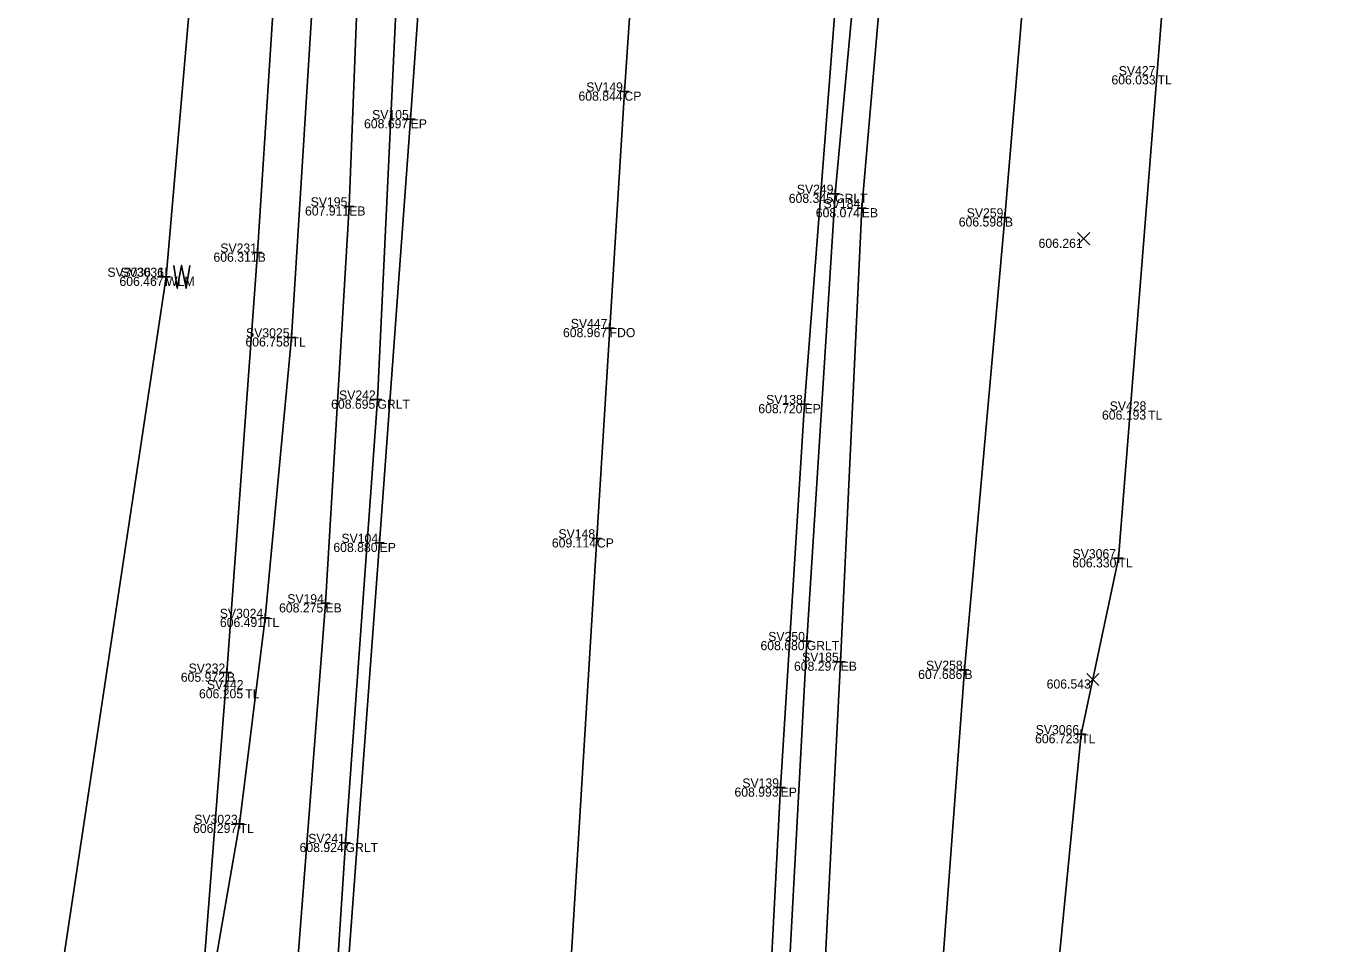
# Model space of a CAD drawing. Extents: x -2 to 1979875, y -2 to 232027.
# Drawn here: x 1978751.3 to 1978823.1, y 231361.9 to 231412.1 of the extents above; entities that cross this region are included whole.
import ezdxf

# ---------------------------------------------------------------- set-up
doc = ezdxf.new("R2010")
doc.units = 0
for name, color, linetype in [('_CIVIL_CONSTRUCTION', 7, 'Continuous'), ('GE_P_Alignment', 7, 'Continuous'), ('GE_P_Alignment_1000_Curve_Data', 7, 'Continuous'), ('GE_P_Alignment_100_Curve_Data', 7, 'Continuous'), ('GE_P_Alignment_500_Curve_Data', 7, 'Continuous'), ('GE_X_Alignment', 7, 'Continuous'), ('GE_X_Alignment_1000_Curve_Data', 7, 'Continuous'), ('GE_X_Alignment_1000_Stations', 7, 'Continuous'), ('GE_X_Alignment_100_Curve_Data', 7, 'Continuous'), ('GE_X_Alignment_100_Stations', 7, 'Continuous'), ('SC_Scratch1', 7, 'Continuous'), ('SV_X_Random_Point', 7, 'Continuous'), ('UT_X_Water', 7, 'Continuous'), ('UT_X_Water_Cells', 7, 'Continuous')]:
    doc.layers.add(name, color=color, linetype=linetype)

msp = doc.modelspace()

# ---------------------------------------------------------------- linework, layer by layer
at = {"layer": 'GE_P_Alignment'}
for points in [[(1978861.689, 231782.415), (1978851.853, 231763.969), (1978841.987, 231745.294), (1978832.802, 231726.204), (1978823.63, 231707.125), (1978815.734, 231686.751), (1978809.08, 231664.461), (1978799.472, 231640.53), (1978791.914, 231616.771), (1978786.956, 231593.117), (1978782.497, 231568.131), (1978778.452, 231542.695), (1978775.331, 231517.531), (1978773.11, 231494.147), (1978771.443, 231473.021), (1978766.839, 231446.726), (1978765.415, 231421.944), (1978763.995, 231399.725), (1978762.317, 231376.717), (1978760.52, 231353.776), (1978758.484, 231331.627), (1978756.746, 231315.247), (1978755.236, 231305.004), (1978757.214, 231296.936)], [(1978796.543, 231298.857), (1978798.274, 231324.443), (1978800.704, 231350.055), (1978802.691, 231376.873), (1978804.911, 231401.653), (1978806.885, 231425.398), (1978807.692, 231450.453), (1978809.926, 231474.524), (1978811.781, 231491.704), (1978814.624, 231521.225), (1978818.445, 231546.214), (1978822.849, 231572.066), (1978827.059, 231594.68), (1978834.582, 231618.811), (1978841.486, 231643.192), (1978848.448, 231666.52), (1978859.661, 231691.186), (1978869.566, 231712.589), (1978880.404, 231735.407), (1978890.398, 231756.483), (1978895.241, 231765.92)]]:
    msp.add_lwpolyline(points, dxfattribs=at)
at = {"layer": 'GE_P_Alignment_1000_Curve_Data'}
for points in [[(1978733.125, 231254.651), (1978737.318, 231281.706), (1978740.694, 231296.926), (1978742.413, 231306.837), (1978748.228, 231322.336), (1978755.317, 231333.122), (1978758.78, 231344.165), (1978763.011, 231368.433), (1978764.4, 231379.716), (1978765.858, 231395.082), (1978767.238, 231417.341), (1978767.097, 231431.457), (1978767.532, 231441.077), (1978768.449, 231451.786), (1978770.871, 231461.5), (1978774.002, 231474.92), (1978775.889, 231489.026), (1978776.895, 231504.336), (1978777.94, 231514.653)], [(1978800.253, 231250.204), (1978805.284, 231291.391), (1978804.508, 231297.592), (1978804.78, 231306.073), (1978804.463, 231312.372), (1978805.146, 231324.315), (1978805.161, 231336.373), (1978807.189, 231350.111), (1978807.848, 231360.671), (1978809.086, 231373.348), (1978811.125, 231382.982), (1978814.162, 231421.098), (1978816.965, 231468.048), (1978822.427, 231510.515)]]:
    msp.add_lwpolyline(points, dxfattribs=at)
at = {"layer": 'GE_P_Alignment_100_Curve_Data'}
for points in [[(1978764.438, 231298.773), (1978765.712, 231320.829), (1978767.378, 231345.616), (1978768.807, 231367.39), (1978770.554, 231391.673), (1978771.722, 231416.416), (1978771.842, 231435.288), (1978771.576, 231449.202)], [(1978801.365, 231447.686), (1978797.734, 231425.84), (1978795.609, 231402.949), (1978794.056, 231378.448), (1978792.74, 231353.579), (1978790.842, 231329.19), (1978789.312, 231307.337), (1978788.697, 231297.789)]]:
    msp.add_lwpolyline(points, dxfattribs=at)
at = {"layer": 'GE_P_Alignment_500_Curve_Data'}
for p, q in [((1978783.265, 231395.844), (1978783.265, 231395.344)), ((1978783.015, 231395.594), (1978783.515, 231395.594)), ((1978783.265, 231395.594), (1978783.265, 231395.594))]:
    msp.add_line(p, q, dxfattribs=at)
at = {"layer": 'GE_X_Alignment_1000_Curve_Data'}
msp.add_lwpolyline([(1978776.88, 231293.019), (1978778.313, 231315.451), (1978779.686, 231337.763), (1978781.119, 231360.475), (1978782.569, 231384.073), (1978784.079, 231408.548), (1978785.737, 231433.04), (1978787.352, 231456.369), (1978789.204, 231480.117), (1978791.477, 231503.648), (1978794.349, 231526.784), (1978797.796, 231550.891), (1978801.515, 231572.898), (1978806.442, 231596.208), (1978812.098, 231619.057), (1978818.629, 231640.775), (1978826, 231662.112), (1978835.057, 231685.412), (1978844.843, 231707.874), (1978854.489, 231728.841), (1978864.575, 231749.812), (1978877.222, 231774.568)], dxfattribs=at)
at = {"layer": 'GE_X_Alignment_1000_Stations'}
for points in [[(1978764.463, 231293.7), (1978765.973, 231315.536), (1978767.501, 231337.797), (1978768.95, 231360.619), (1978770.673, 231383.826), (1978772.372, 231407.034), (1978773.964, 231429.759), (1978775.312, 231448.487), (1978777.194, 231472.049), (1978779.086, 231494.381), (1978781.387, 231516.708), (1978784.451, 231540.773), (1978787.814, 231562.2), (1978793.416, 231590.474), (1978799.132, 231614.141), (1978805.307, 231636.271), (1978811.99, 231656.714), (1978821.006, 231681.034), (1978832.082, 231707.98), (1978843.434, 231732.641), (1978854.786, 231756.844), (1978866.633, 231780.181)], [(1978887.054, 231769.497), (1978875.688, 231747.111), (1978865.322, 231725.635), (1978856.257, 231705.079), (1978847.493, 231684.376), (1978839.463, 231663.377), (1978831.793, 231640.155), (1978824.647, 231616.117), (1978817.773, 231591.521), (1978812.873, 231567.295), (1978809.011, 231544.227), (1978805.416, 231519.882), (1978802.367, 231496.191), (1978799.68, 231465.625), (1978797.956, 231442.353), (1978795.891, 231416.691), (1978793.937, 231391.428), (1978792.627, 231370.424), (1978791.336, 231345.811), (1978789.97, 231322.684), (1978787.965, 231301.579), (1978787.711, 231292.48)]]:
    msp.add_lwpolyline(points, dxfattribs=at)
at = {"layer": 'GE_X_Alignment_100_Curve_Data'}
for p, q in [((1978783.829, 231408.548), (1978784.329, 231408.548)), ((1978784.079, 231408.798), (1978784.079, 231408.298)), ((1978784.079, 231408.548), (1978784.079, 231408.548)), ((1978772.372, 231407.284), (1978772.372, 231406.784)), ((1978772.122, 231407.034), (1978772.622, 231407.034)), ((1978772.372, 231407.034), (1978772.372, 231407.034)), ((1978795.359, 231402.949), (1978795.859, 231402.949)), ((1978795.609, 231403.199), (1978795.609, 231402.699)), ((1978795.609, 231402.949), (1978795.609, 231402.949)), ((1978768.759, 231402.257), (1978769.259, 231402.257)), ((1978769.009, 231402.507), (1978769.009, 231402.007)), ((1978769.009, 231402.257), (1978769.009, 231402.257)), ((1978796.821, 231402.161), (1978797.321, 231402.161)), ((1978797.071, 231402.411), (1978797.071, 231401.911)), ((1978797.071, 231402.161), (1978797.071, 231402.161)), ((1978804.661, 231401.653), (1978805.161, 231401.653)), ((1978804.911, 231401.903), (1978804.911, 231401.403)), ((1978804.911, 231401.653), (1978804.911, 231401.653)), ((1978763.995, 231399.975), (1978763.995, 231399.475)), ((1978763.745, 231399.725), (1978764.245, 231399.725)), ((1978763.995, 231399.725), (1978763.995, 231399.725)), ((1978758.981, 231398.651), (1978758.981, 231398.151)), ((1978758.731, 231398.401), (1978759.231, 231398.401)), ((1978758.981, 231398.401), (1978758.981, 231398.401)), ((1978765.608, 231395.082), (1978766.108, 231395.082)), ((1978765.858, 231395.332), (1978765.858, 231394.832)), ((1978765.858, 231395.082), (1978765.858, 231395.082)), ((1978770.304, 231391.673), (1978770.804, 231391.673)), ((1978770.554, 231391.923), (1978770.554, 231391.423)), ((1978770.554, 231391.673), (1978770.554, 231391.673)), ((1978793.687, 231391.428), (1978794.187, 231391.428)), ((1978793.937, 231391.678), (1978793.937, 231391.178)), ((1978793.937, 231391.428), (1978793.937, 231391.428)), ((1978782.569, 231384.323), (1978782.569, 231383.823)), ((1978770.423, 231383.826), (1978770.923, 231383.826)), ((1978770.673, 231384.076), (1978770.673, 231383.576)), ((1978770.673, 231383.826), (1978770.673, 231383.826)), ((1978782.319, 231384.073), (1978782.819, 231384.073)), ((1978782.569, 231384.073), (1978782.569, 231384.073)), ((1978810.875, 231382.982), (1978811.375, 231382.982)), ((1978811.125, 231383.232), (1978811.125, 231382.732)), ((1978811.125, 231382.982), (1978811.125, 231382.982)), ((1978767.705, 231380.765), (1978767.705, 231380.265)), ((1978764.4, 231379.966), (1978764.4, 231379.466)), ((1978767.455, 231380.515), (1978767.955, 231380.515)), ((1978767.705, 231380.515), (1978767.705, 231380.515)), ((1978764.15, 231379.716), (1978764.65, 231379.716)), ((1978764.4, 231379.716), (1978764.4, 231379.716)), ((1978793.806, 231378.448), (1978794.306, 231378.448)), ((1978794.056, 231378.698), (1978794.056, 231378.198)), ((1978794.056, 231378.448), (1978794.056, 231378.448)), ((1978762.317, 231376.967), (1978762.317, 231376.467)), ((1978795.662, 231377.319), (1978796.162, 231377.319)), ((1978795.912, 231377.569), (1978795.912, 231377.069)), ((1978795.912, 231377.319), (1978795.912, 231377.319)), ((1978802.691, 231377.123), (1978802.691, 231376.623)), ((1978762.067, 231376.717), (1978762.567, 231376.717)), ((1978762.317, 231376.717), (1978762.317, 231376.717)), ((1978802.441, 231376.873), (1978802.941, 231376.873)), ((1978802.691, 231376.873), (1978802.691, 231376.873)), ((1978808.836, 231373.348), (1978809.336, 231373.348)), ((1978809.086, 231373.598), (1978809.086, 231373.098)), ((1978809.086, 231373.348), (1978809.086, 231373.348)), ((1978792.627, 231370.674), (1978792.627, 231370.174)), ((1978792.377, 231370.424), (1978792.877, 231370.424)), ((1978792.627, 231370.424), (1978792.627, 231370.424)), ((1978762.761, 231368.433), (1978763.261, 231368.433)), ((1978763.011, 231368.683), (1978763.011, 231368.183)), ((1978763.011, 231368.433), (1978763.011, 231368.433)), ((1978768.807, 231367.64), (1978768.807, 231367.14)), ((1978768.557, 231367.39), (1978769.057, 231367.39)), ((1978768.807, 231367.39), (1978768.807, 231367.39))]:
    msp.add_line(p, q, dxfattribs=at)
at = {"layer": 'SC_Scratch1'}
for points in [[(1978762.241, 231295.643), (1978763.575, 231312.653), (1978764.638, 231334.283), (1978765.818, 231356.042), (1978767.705, 231380.515), (1978769.009, 231402.257), (1978769.844, 231423.935), (1978772.522, 231443.246), (1978774.792, 231466.077), (1978776.974, 231489.898), (1978779.234, 231514.617), (1978782.489, 231539.582), (1978786.101, 231563.808), (1978790.249, 231586.35), (1978795.964, 231611.211), (1978802.838, 231634.974), (1978810.373, 231657.227), (1978818.1, 231678.589), (1978826.474, 231699.286), (1978835.162, 231719.41), (1978844.319, 231739.683), (1978854.914, 231761.571), (1978865.037, 231781.151)], [(1978888.808, 231768.485), (1978877.882, 231747.21), (1978866.825, 231724.389), (1978857.223, 231702.339), (1978848.244, 231681.507), (1978839.526, 231658.205), (1978831.772, 231633.737), (1978825.103, 231611.479), (1978819.562, 231589.918), (1978815.237, 231567.914), (1978810.741, 231543.659), (1978807.235, 231520.012), (1978805.099, 231498.598), (1978802.191, 231475.113), (1978800.521, 231451.185), (1978799.203, 231426.897), (1978797.071, 231402.161), (1978795.912, 231377.319), (1978794.635, 231352.241), (1978792.961, 231328.96), (1978791.062, 231305.225), (1978790.036, 231294.396)]]:
    msp.add_lwpolyline(points, dxfattribs=at)
at = {"layer": 'SV_X_Random_Point'}
for p, q in [((1978808.887, 231400.153), (1978809.553, 231400.821)), ((1978808.887, 231400.821), (1978809.553, 231400.153)), ((1978809.386, 231376.011), (1978810.052, 231376.679)), ((1978809.386, 231376.679), (1978810.052, 231376.011))]:
    msp.add_line(p, q, dxfattribs=at)
at = {"layer": 'UT_X_Water'}
msp.add_lwpolyline([(1978712.49, 231209.97), (1978714.812, 231240.893), (1978716.641, 231256.079), (1978724.417, 231285.176), (1978739.059, 231319.254), (1978749.995, 231338.561), (1978758.981, 231398.401), (1978764.286, 231459.71)], dxfattribs=at)
at = {"layer": 'UT_X_Water_Cells'}
for p, q in [((1978758.981, 231397.901), (1978758.981, 231398.901)), ((1978758.981, 231398.401), (1978758.505, 231398.401))]:
    msp.add_line(p, q, dxfattribs=at)
msp.add_lwpolyline([(1978759.403, 231399.026), (1978759.59, 231397.776), (1978759.836, 231399.026), (1978760.082, 231397.776), (1978760.279, 231399.026)], dxfattribs=at)

# ---------------------------------------------------------------- texts
at = {"layer": '_CIVIL_CONSTRUCTION'}
for s, p in [('606.033', (1978810.741, 231408.939)), ('608.844', (1978781.563, 231408.048)), ('608.697', (1978769.821, 231406.534)), ('608.345', (1978793.074, 231402.449)), ('607.911', (1978766.591, 231401.757)), ('608.074', (1978794.555, 231401.661)), ('606.598', (1978802.381, 231401.153)), ('606.261', (1978806.75, 231399.987)), ('606.311', (1978761.577, 231399.225)), ('606.467', (1978756.43, 231397.901)), ('606.467', (1978756.43, 231397.901)), ('608.967', (1978780.714, 231395.094)), ('606.758', (1978763.328, 231394.582)), ('608.695', (1978768.019, 231391.173)), ('608.720', (1978791.407, 231390.928)), ('606.193', (1978810.224, 231390.576)), ('608.880', (1978768.143, 231383.326)), ('609.114', (1978780.105, 231383.573)), ('606.330', (1978808.595, 231382.482)), ('608.275', (1978765.17, 231380.015)), ('606.491', (1978761.93, 231379.216)), ('608.680', (1978791.526, 231377.948)), ('608.297', (1978793.361, 231376.819)), ('605.972', (1978759.789, 231376.217)), ('607.686', (1978800.159, 231376.373)), ('606.543', (1978807.194, 231375.845)), ('606.205', (1978760.784, 231375.311)), ('606.723', (1978806.561, 231372.848)), ('608.993', (1978790.102, 231369.924)), ('606.297', (1978760.46, 231367.933)), ('608.924', (1978766.291, 231366.89))]:
    msp.add_text(s, height=0.5, dxfattribs=at).set_placement(p)
at = {"layer": 'GE_X_Alignment'}
for s, p in [('SV427', (1978811.141, 231409.439)), ('SV149', (1978781.985, 231408.548)), ('SV105', (1978770.263, 231407.034)), ('SV249', (1978793.515, 231402.949)), ('SV195', (1978766.9, 231402.257)), ('SV184', (1978794.982, 231402.161)), ('SV259', (1978802.817, 231401.653)), ('SV231', (1978761.952, 231399.725)), ('SV3036_1', (1978755.773, 231398.401)), ('SV3036', (1978756.487, 231398.401)), ('SV447', (1978781.14, 231395.594)), ('SV3025', (1978763.361, 231395.082)), ('SV242', (1978768.453, 231391.673)), ('SV138', (1978791.834, 231391.428)), ('SV428', (1978810.646, 231391.076)), ('SV104', (1978768.584, 231383.826)), ('SV148', (1978780.466, 231384.073)), ('SV3067', (1978808.612, 231382.982)), ('SV194', (1978765.616, 231380.515)), ('SV3024', (1978761.923, 231379.716)), ('SV250', (1978791.952, 231378.448)), ('SV185', (1978793.803, 231377.319)), ('SV232', (1978760.216, 231376.717)), ('SV258', (1978800.588, 231376.873)), ('SV442', (1978761.218, 231375.811)), ('SV3066', (1978806.592, 231373.348)), ('SV139', (1978790.533, 231370.424)), ('SV3023', (1978760.525, 231368.433)), ('SV241', (1978766.764, 231367.39))]:
    msp.add_text(s, height=0.5, dxfattribs=at).set_placement(p)
at = {"layer": 'GE_X_Alignment_100_Stations'}
for s, p in [('TL', (1978813.266, 231408.939)), ('CP', (1978784.079, 231408.048)), ('EP', (1978772.372, 231406.534)), ('GRLT', (1978795.609, 231402.449)), ('EB', (1978769.009, 231401.757)), ('EB', (1978797.071, 231401.661)), ('B', (1978804.911, 231401.153)), ('B', (1978763.995, 231399.225)), ('WL', (1978758.981, 231397.901)), ('WLM', (1978758.981, 231397.901)), ('FDO', (1978783.265, 231395.094)), ('TL', (1978765.858, 231394.582)), ('GRLT', (1978770.554, 231391.173)), ('EP', (1978793.937, 231390.928)), ('TL', (1978812.749, 231390.576)), ('EP', (1978770.673, 231383.326)), ('CP', (1978782.569, 231383.573)), ('TL', (1978811.125, 231382.482)), ('EB', (1978767.705, 231380.015)), ('TL', (1978764.4, 231379.216)), ('GRLT', (1978794.056, 231377.948)), ('EB', (1978795.912, 231376.819)), ('B', (1978762.317, 231376.217)), ('B', (1978802.691, 231376.373)), ('TL', (1978763.319, 231375.311)), ('TL', (1978809.086, 231372.848)), ('EP', (1978792.627, 231369.924)), ('TL', (1978763.011, 231367.933)), ('GRLT', (1978768.807, 231366.89))]:
    msp.add_text(s, height=0.5, dxfattribs=at).set_placement(p)

doc.saveas('drawing.dxf')
